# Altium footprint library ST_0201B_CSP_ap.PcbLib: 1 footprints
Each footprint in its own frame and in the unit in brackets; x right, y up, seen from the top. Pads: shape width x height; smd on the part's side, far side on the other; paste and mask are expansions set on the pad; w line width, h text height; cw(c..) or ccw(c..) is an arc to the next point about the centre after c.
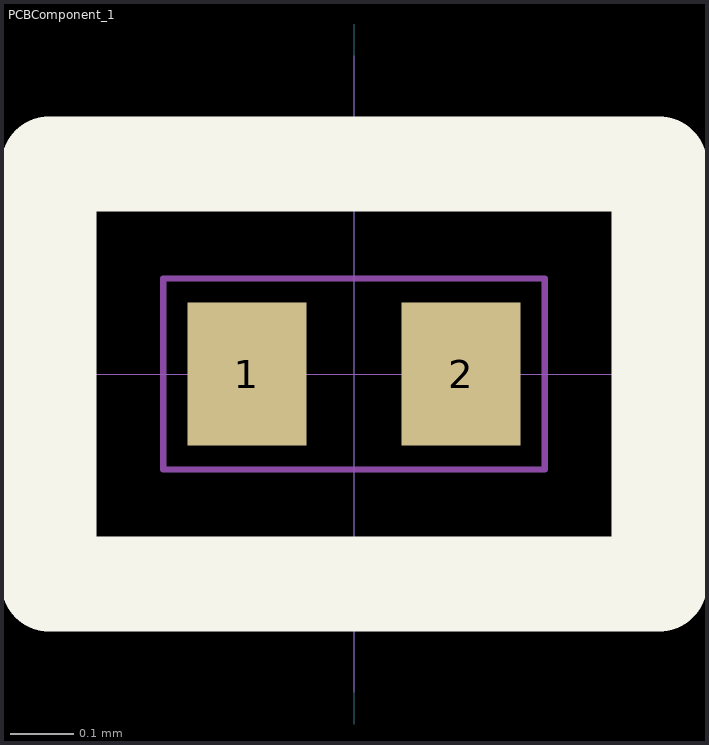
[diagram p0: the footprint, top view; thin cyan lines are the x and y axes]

## PCBComponent_1 [mm]
pads (2):
  rect 0.187x0.225 smd paste-0.01 mask+0.025: 1(-0.168,0) 2(0.169,0)
Top Overlay:
  lines w0.15: -0.48,-0.33 -0.48,0.33 0.48,0.33 0.48,-0.33 -0.48,-0.33
Mechanical 15:
  lines w0.001: -0.5,0 0.5,0 ; 0,-0.5 0,0.5
  lines w0.01: -0.3,-0.15 -0.3,0.15 0.3,0.15 0.3,-0.15 -0.3,-0.15
3D body: height 0.33, standoff 0, extent -0.3,-0.15 0.3,0.15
